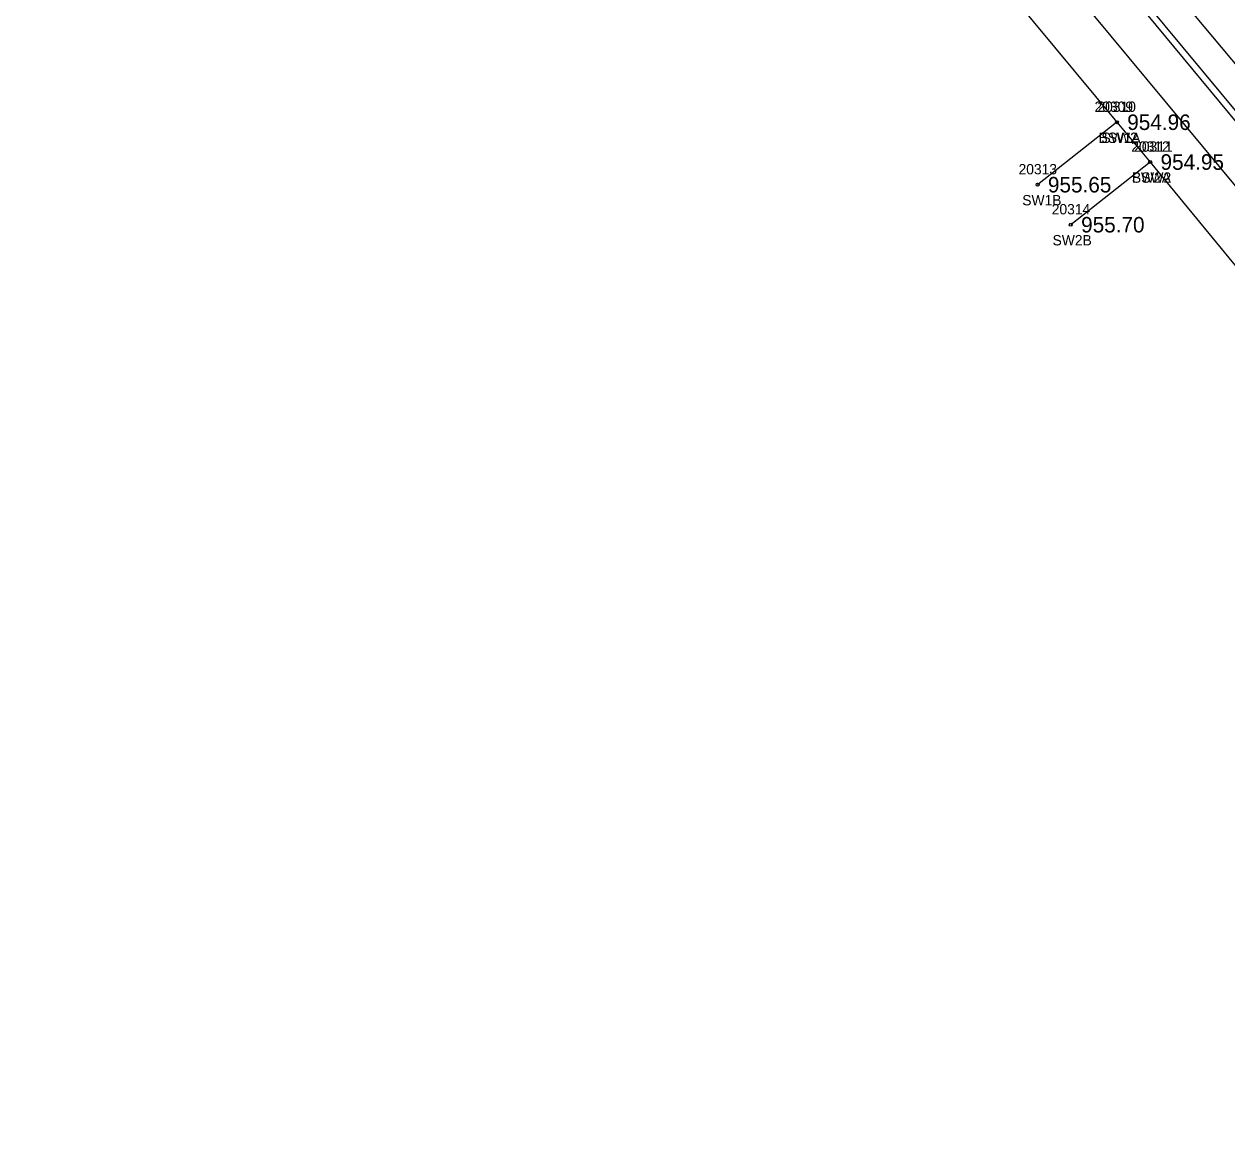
# Model space of a CAD drawing. Extents: x 1576181 to 1577685, y 1099396 to 1101490.
# Drawn here: x 1576365.1 to 1576481.4, y 1099397.7 to 1099504.3 of the extents above; entities that cross this region are included whole.
import ezdxf

# ---------------------------------------------------------------- set-up
doc = ezdxf.new("R2010")
doc.units = 0
for name, color, linetype in [('RD_DTM_BkLn2', 7, 'Continuous'), ('RD_EX_Conc', 7, 'Continuous'), ('RD_EX_Conc_txCode', 7, 'Continuous'), ('RD_EX_Road', 7, 'Continuous'), ('RD_EX_TX_Conc_ELEV', 7, 'Continuous'), ('RD_SMD_Locator', 7, 'Continuous')]:
    doc.layers.add(name, color=color, linetype=linetype)

msp = doc.modelspace()

# ---------------------------------------------------------------- linework, layer by layer
at = {"layer": 'RD_DTM_BkLn2'}
msp.add_lwpolyline([(1576411.94, 1099579.95), (1576414.49, 1099576.96), (1576418.07, 1099572.26), (1576420.73, 1099569.37), (1576424.53, 1099564.75), (1576430.75, 1099556.96), (1576462.11, 1099519.29), (1576494.91, 1099479.63), (1576525.82, 1099442.2), (1576557.4, 1099404.07)], dxfattribs=at)
at = {"layer": 'RD_EX_Conc'}
for p, q in [((1576470.78, 1099494.84), (1576463.11, 1099488.8)), ((1576474, 1099490.99), (1576466.32, 1099484.93))]:
    msp.add_line(p, q, dxfattribs=at)
for points in [[(1576396.55, 1099574.21), (1576400.94, 1099578.26), (1576405.4, 1099581.45), (1576408.35, 1099582.39), (1576411.1, 1099581.54), (1576412.48, 1099580.16), (1576412.48, 1099580.16), (1576431.43, 1099557.37), (1576462.58, 1099519.63), (1576495.36, 1099480.14), (1576526.3, 1099442.62), (1576558.03, 1099404.43)], [(1576424.53, 1099564.75), (1576421.54, 1099562.11), (1576427.77, 1099554.24), (1576491.4, 1099477.63), (1576522.92, 1099439.59), (1576554.46, 1099401.18)], [(1576417.79, 1099558.83), (1576419.81, 1099556.41), (1576422.78, 1099552.79), (1576443.67, 1099527.67), (1576447.39, 1099523.04), (1576450.38, 1099519.36), (1576454.58, 1099514.36), (1576470.78, 1099494.84), (1576474, 1099490.99), (1576488.02, 1099473.93), (1576497.44, 1099462.54), (1576500.63, 1099458.76), (1576516.67, 1099439.27), (1576520.69, 1099434.46), (1576523.68, 1099430.77), (1576527.93, 1099425.88), (1576541.66, 1099409.22), (1576544.52, 1099405.7), (1576551.21, 1099397.69)]]:
    msp.add_lwpolyline(points, dxfattribs=at)
at = {"layer": 'RD_EX_Road'}
msp.add_lwpolyline([(1576365.09, 1099547.1), (1576400.46, 1099578.87), (1576404.99, 1099582.28), (1576408.27, 1099583.27), (1576411.47, 1099582.29), (1576413.12, 1099580.85), (1576414.82, 1099582.11), (1576433.7, 1099559), (1576464.95, 1099521.11), (1576497.8, 1099481.91), (1576528.73, 1099444.46), (1576560.01, 1099406.61)], dxfattribs=at)
at = {"layer": 'RD_SMD_Locator'}
for centre in [(1576470.78, 1099494.84), (1576470.78, 1099494.84), (1576474, 1099490.99), (1576474, 1099490.99), (1576463.11, 1099488.8), (1576466.32, 1099484.93)]:
    msp.add_circle(centre, 0.15, dxfattribs=at)

# ---------------------------------------------------------------- texts
at = {"layer": 'RD_EX_Conc_txCode'}
for s, p in [('20309', (1576468.62, 1099495.84)), ('20310', (1576468.9, 1099495.84)), ('BSW2', (1576469.01, 1099492.84)), ('SW1A', (1576469.28, 1099492.84)), ('20312', (1576472.17, 1099491.99)), ('20311', (1576472.45, 1099491.99)), ('20313', (1576461.27, 1099489.8)), ('SW2A', (1576472.22, 1099488.99)), ('BSW2', (1576472.24, 1099488.99)), ('SW1B', (1576461.63, 1099486.8)), ('20314', (1576464.48, 1099485.93)), ('SW2B', (1576464.56, 1099482.93))]:
    msp.add_text(s, height=1, dxfattribs=at).set_placement(p)
at = {"layer": 'RD_EX_TX_Conc_ELEV'}
for s, p in [('954.96', (1576471.78, 1099494.09)), ('954.96', (1576471.78, 1099494.09)), ('954.95', (1576475, 1099490.24)), ('954.95', (1576475, 1099490.24)), ('955.65', (1576464.11, 1099488.05)), ('955.70', (1576467.32, 1099484.18))]:
    msp.add_text(s, height=1.5, dxfattribs=at).set_placement(p)

doc.saveas('drawing.dxf')
